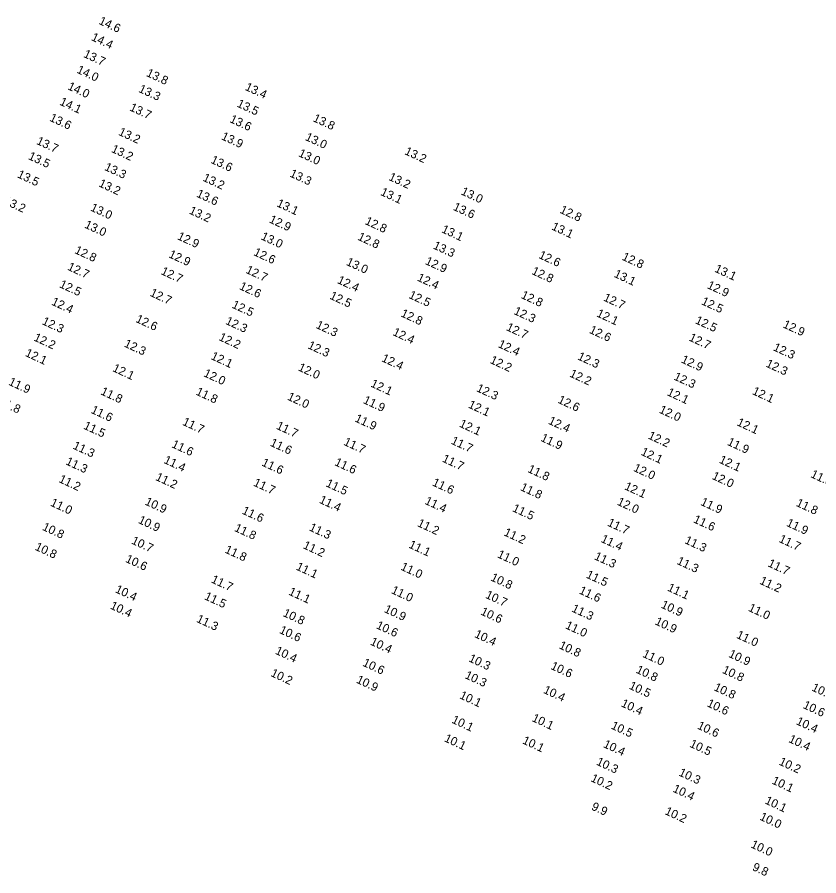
# Model space of a CAD drawing. Extents: x 988130 to 1132882, y 654656 to 841453.
# Drawn here: x 1100298 to 1100769, y 701435 to 701939 of the extents above; entities that cross this region are included whole.
import ezdxf

# ---------------------------------------------------------------- set-up
doc = ezdxf.new("R2010")
doc.units = 0
doc.layers.add('V-TOPO-SOUN', color=7, linetype='Continuous')

msp = doc.modelspace()

# ---------------------------------------------------------------- texts
at = {"layer": 'V-TOPO-SOUN'}
for s, p in [('14.6 ', (1100345.67, 701935.27)), ('14.4 ', (1100341.26, 701925.74)), ('13.7 ', (1100336.7, 701915.84)), ('14.0 ', (1100332.74, 701906.59)), ('13.8 ', (1100373.55, 701904.66)), ('14.0 ', (1100327.4, 701896.87)), ('13.3 ', (1100369.05, 701895.34)), ('13.4 ', (1100431.53, 701896.5)), ('14.1 ', (1100322.69, 701887.81)), ('13.7 ', (1100363.77, 701884.48)), ('13.5 ', (1100426.76, 701886.7)), ('13.6 ', (1100316.77, 701878.4)), ('13.6 ', (1100422.52, 701877.6)), ('13.8 ', (1100471.4, 701878.12)), ('13.2 ', (1100357.23, 701870.12)), ('13.9 ', (1100417.58, 701867.52)), ('13.0 ', (1100466.84, 701867.09)), ('13.7 ', (1100309.09, 701864.77)), ('13.2 ', (1100353.03, 701860.09)), ('13.0 ', (1100462.87, 701857.59)), ('13.2 ', (1100525.19, 701858.76)), ('13.5 ', (1100304.29, 701855.88)), ('13.6 ', (1100411.38, 701853.69)), ('13.3 ', (1100349.01, 701849.51)), ('13.5 ', (1100297.83, 701845.17)), ('13.2 ', (1100406.71, 701843.19)), ('13.3 ', (1100457.75, 701845.67)), ('13.2 ', (1100515.83, 701843.66)), ('13.2 ', (1100345.62, 701839.89)), ('13.6 ', (1100403, 701833.82)), ('13.1 ', (1100511.05, 701834.82)), ('13.0 ', (1100558.3, 701835.15)), ('13.2 ', (1100289.9, 701829.64)), ('13.1 ', (1100450.08, 701828.18)), ('13.0 ', (1100340.77, 701825.68)), ('13.2 ', (1100398.68, 701823.92)), ('13.6 ', (1100553.65, 701826.11)), ('12.8 ', (1100616.29, 701824.37)), ('12.9 ', (1100445.68, 701818.71)), ('12.8 ', (1100501.94, 701817.74)), ('13.0 ', (1100337.32, 701815.64)), ('13.1 ', (1100546.85, 701812.93)), ('13.1 ', (1100611.46, 701814.56)), ('12.9 ', (1100391.77, 701808.84)), ('13.0 ', (1100440.87, 701808.76)), ('12.8 ', (1100497.63, 701808.55)), ('13.3 ', (1100541.91, 701803.4)), ('12.8 ', (1100331.5, 701800.68)), ('12.9 ', (1100386.68, 701798.26)), ('12.6 ', (1100436.56, 701799.48)), ('12.6 ', (1100603.88, 701797.83)), ('12.8 ', (1100652.79, 701796.81)), ('13.0 ', (1100490.9, 701793.78)), ('12.9 ', (1100537.28, 701794.27)), ('12.7 ', (1100327.29, 701790.92)), ('12.7 ', (1100382.16, 701788.34)), ('12.7 ', (1100431.94, 701789.12)), ('12.8 ', (1100599.77, 701788.43)), ('13.1 ', (1100648.07, 701786.75)), ('13.1 ', (1100707.14, 701789.78)), ('12.4 ', (1100485.68, 701783.11)), ('12.4 ', (1100532.53, 701784.58)), ('12.5 ', (1100322.58, 701780.63)), ('12.6 ', (1100428.18, 701779.54)), ('12.9 ', (1100702.78, 701780.11)), ('12.7 ', (1100375.68, 701775.63)), ('12.5 ', (1100481.23, 701773.91)), ('12.5 ', (1100527.63, 701774.36)), ('12.8 ', (1100593.52, 701774.34)), ('12.7 ', (1100641.86, 701772.86)), ('12.4 ', (1100317.89, 701770.43)), ('12.5 ', (1100423.81, 701768.65)), ('12.5 ', (1100699.39, 701770.65)), ('12.8 ', (1100522.95, 701763.57)), ('12.3 ', (1100589.28, 701764.95)), ('12.1 ', (1100637.86, 701763.55)), ('12.3 ', (1100312.36, 701758.95)), ('12.6 ', (1100367.35, 701760.29)), ('12.3 ', (1100420.05, 701759.14)), ('12.3 ', (1100473.12, 701756.78)), ('12.5 ', (1100695.78, 701759.52)), ('12.9 ', (1100747.24, 701757.09)), ('12.4 ', (1100518.21, 701752.57)), ('12.7 ', (1100584.83, 701755.46)), ('12.6 ', (1100633.59, 701753.87)), ('12.2 ', (1100307.49, 701749.41)), ('12.2 ', (1100416.14, 701749.64)), ('12.7 ', (1100692.09, 701749.37)), ('12.3 ', (1100360.54, 701745.83)), ('12.3 ', (1100468.34, 701744.82)), ('12.4 ', (1100580.04, 701745.52)), ('12.3 ', (1100741.52, 701743.64)), ('12.1 ', (1100302.46, 701740.33)), ('12.1 ', (1100411.48, 701738.49)), ('12.4 ', (1100511.66, 701737.22)), ('12.2 ', (1100575.3, 701736.19)), ('12.3 ', (1100626.71, 701738.3)), ('12.9 ', (1100687.53, 701736.49)), ('12.1 ', (1100353.74, 701731.4)), ('12.0 ', (1100462.68, 701731.84)), ('12.3 ', (1100737.23, 701734.07)), ('12.0 ', (1100407.21, 701728.41)), ('12.2 ', (1100622.03, 701728.22)), ('12.3 ', (1100683.21, 701726.48)), ('11.9 ', (1100292.71, 701723.4)), ('12.1 ', (1100505.25, 701722.35)), ('11.8 ', (1100346.78, 701717.76)), ('11.8 ', (1100402.65, 701717.62)), ('12.3 ', (1100567.32, 701719.64)), ('12.1 ', (1100679.22, 701717.27)), ('12.1 ', (1100729.25, 701717.92)), ('11.8 ', (1100286.92, 701711.75)), ('12.0 ', (1100456.34, 701714.67)), ('11.9 ', (1100500.86, 701712.63)), ('12.6 ', (1100615.11, 701712.84)), ('11.6 ', (1100341.06, 701706.9)), ('12.1 ', (1100562.51, 701710.03)), ('12.0 ', (1100674.59, 701707.02)), ('11.9 ', (1100495.95, 701701.88)), ('11.5 ', (1100336.72, 701697.61)), ('11.7 ', (1100394.76, 701699.9)), ('11.7 ', (1100449.84, 701697.57)), ('12.1 ', (1100557.28, 701698.8)), ('12.4 ', (1100609.54, 701700.51)), ('12.1 ', (1100720.21, 701699.61)), ('12.2 ', (1100668.07, 701691.82)), ('11.3 ', (1100330.46, 701685.91)), ('11.6 ', (1100388.42, 701686.74)), ('11.6 ', (1100446.24, 701687.63)), ('11.7 ', (1100489.41, 701688.14)), ('11.7 ', (1100552.45, 701688.79)), ('11.9 ', (1100605.05, 701690.47)), ('11.9 ', (1100714.58, 701688.11)), ('12.1 ', (1100663.88, 701682.28)), ('11.3 ', (1100326.25, 701676.69)), ('11.4 ', (1100383.83, 701677.5)), ('11.6 ', (1100441.28, 701675.98)), ('11.6 ', (1100484.09, 701676.19)), ('11.7 ', (1100547.24, 701678.29)), ('12.1 ', (1100709.79, 701677.65)), ('11.8 ', (1100597.43, 701672.19)), ('12.0 ', (1100659.47, 701672.86)), ('11.2 ', (1100322.2, 701666.28)), ('11.2 ', (1100378.99, 701667.48)), ('12.0 ', (1100705.62, 701668.12)), ('11.8 ', (1100763.52, 701669.15)), ('11.7 ', (1100436.44, 701664.19)), ('11.5 ', (1100478.95, 701663.79)), ('11.6 ', (1100541.42, 701664.31)), ('11.8 ', (1100593.12, 701661.52)), ('12.1 ', (1100654.24, 701662.03)), ('11.0 ', (1100317.26, 701652.43)), ('10.9 ', (1100372.77, 701653.07)), ('11.4 ', (1100475.07, 701654.11)), ('11.4 ', (1100537.05, 701653.49)), ('12.0 ', (1100649.93, 701652.98)), ('11.9 ', (1100698.92, 701652.87)), ('11.8 ', (1100754.96, 701652.29)), ('11.6 ', (1100429.74, 701647.76)), ('11.5 ', (1100588.44, 701649.16)), ('10.9 ', (1100368.83, 701642.28)), ('11.2 ', (1100532.67, 701640.41)), ('11.7 ', (1100644.24, 701640.69)), ('11.6 ', (1100694.68, 701642.65)), ('11.9 ', (1100749.27, 701640.56)), ('10.8 ', (1100312.53, 701638.21)), ('11.8 ', (1100425.27, 701637.58)), ('11.3 ', (1100469.15, 701637.89)), ('10.7 ', (1100364.85, 701630.16)), ('11.2 ', (1100583.44, 701635)), ('11.4 ', (1100640.4, 701631.16)), ('11.3 ', (1100689.58, 701630.38)), ('11.7 ', (1100744.87, 701631.15)), ('10.8 ', (1100308.22, 701626.53)), ('11.2 ', (1100465.56, 701627.44)), ('11.1 ', (1100527.6, 701627.8)), ('11.8 ', (1100419.66, 701624.9)), ('11.0 ', (1100579.61, 701622.11)), ('11.3 ', (1100636.52, 701620.96)), ('10.6 ', (1100361.33, 701619.43)), ('11.1 ', (1100461.46, 701614.89)), ('11.3 ', (1100684.98, 701618.2)), ('11.7 ', (1100738.41, 701616.81)), ('11.0 ', (1100522.86, 701614.85)), ('11.5 ', (1100631.73, 701610.17)), ('11.7 ', (1100411.62, 701607.36)), ('10.8 ', (1100575.71, 701608.53)), ('11.2 ', (1100733.57, 701606.58)), ('10.4 ', (1100355.29, 701601.6)), ('11.1 ', (1100457.09, 701600.19)), ('11.0 ', (1100517.34, 701601.07)), ('11.6 ', (1100627.58, 701600.88)), ('11.1 ', (1100679.46, 701602.55)), ('11.5 ', (1100407.68, 701597.46)), ('10.7 ', (1100572.62, 701598.32)), ('10.4 ', (1100352.37, 701592)), ('10.9 ', (1100513.19, 701589.93)), ('11.3 ', (1100623.24, 701590.29)), ('10.9 ', (1100675.7, 701592.55)), ('11.0 ', (1100726.92, 701590.69)), ('10.8 ', (1100453.75, 701587.63)), ('10.6 ', (1100569.82, 701588.53)), ('11.3 ', (1100402.98, 701584.19)), ('10.6 ', (1100508.48, 701580.45)), ('11.0 ', (1100619.53, 701580.41)), ('10.9 ', (1100672.18, 701582.71)), ('10.6 ', (1100451.67, 701577.66)), ('10.4 ', (1100566.21, 701575.27)), ('11.0 ', (1100719.94, 701574.83)), ('10.4 ', (1100505.03, 701570.87)), ('10.4 ', (1100449.24, 701565.49)), ('10.8 ', (1100615.8, 701568.67)), ('10.3 ', (1100562.78, 701561.03)), ('11.0 ', (1100664.84, 701563.67)), ('10.9 ', (1100715.36, 701563.64)), ('10.6 ', (1100500.56, 701558.44)), ('10.6 ', (1100610.94, 701556.56)), ('10.2 ', (1100446.6, 701552.39)), ('10.3 ', (1100560.56, 701551.15)), ('10.8 ', (1100661.01, 701554.35)), ('10.8 ', (1100711.65, 701554.26)), ('10.9 ', (1100496.82, 701548.49)), ('10.5 ', (1100656.91, 701544.97)), ('10.1 ', (1100557.46, 701539.33)), ('10.4 ', (1100606.63, 701542.51)), ('10.8 ', (1100706.73, 701544.07)), ('10.8 ', (1100764.12, 701543.91)), ('10.4 ', (1100652.25, 701534.61)), ('10.6 ', (1100702.66, 701534.62)), ('10.6 ', (1100759.05, 701533.61)), ('10.1 ', (1100552.84, 701524.98)), ('10.1 ', (1100599.91, 701525.97)), ('10.5 ', (1100646.36, 701521.55)), ('10.6 ', (1100696.99, 701521.54)), ('10.4 ', (1100754.99, 701524.12)), ('10.1 ', (1100548.46, 701514.1)), ('10.1 ', (1100594.33, 701512.84)), ('10.4 ', (1100641.82, 701510.66)), ('10.5 ', (1100692.51, 701510.87)), ('10.4 ', (1100750.58, 701513.66)), ('10.3 ', (1100637.73, 701500.36)), ('10.2 ', (1100744.91, 701500.41)), ('10.3 ', (1100686.09, 701494.02)), ('10.2 ', (1100634.44, 701490.64)), ('10.1 ', (1100740.76, 701489.28)), ('10.4 ', (1100682.6, 701484.5)), ('9.9', (1100634.83, 701474.01)), ('10.1 ', (1100736.68, 701477.58)), ('10.2 ', (1100677.95, 701471.3)), ('10.0 ', (1100733.61, 701468.06)), ('10.0 ', (1100728.38, 701451.79)), ('9.8', (1100729.27, 701438.49))]:
    msp.add_text(s, height=5, rotation=335, dxfattribs=at).set_placement(p)

doc.saveas('drawing.dxf')
